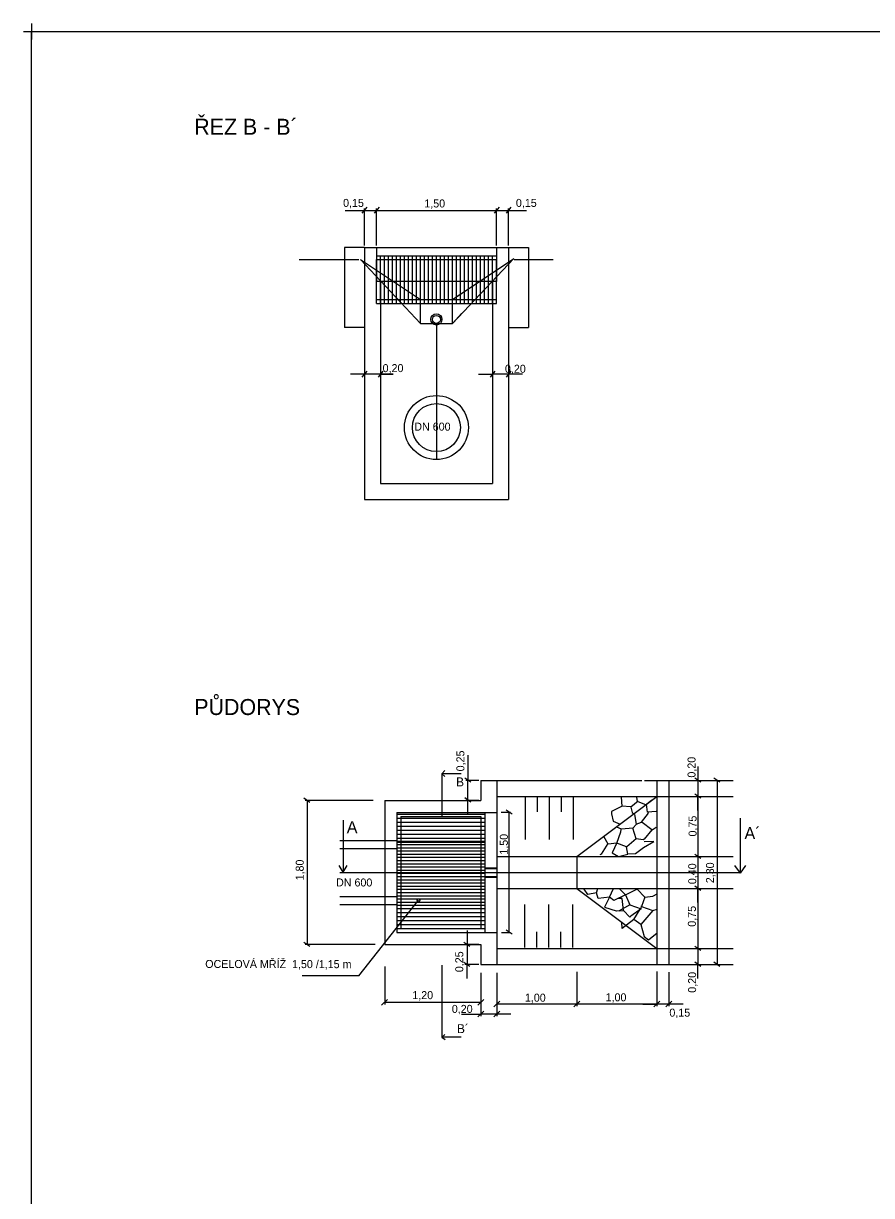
# Model space of a CAD drawing. Extents: x -463166.8 to -463145.6, y -1105023 to -1104993.1.
# Drawn here: x -463166.78 to -463156.18, y -1105007.73 to -1104993.08 of the extents above; entities that cross this region are included whole.
import ezdxf

# ---------------------------------------------------------------- set-up
doc = ezdxf.new("R2010")
doc.units = 0
doc.layers.add('Vrstva 14', color=7, linetype='Continuous')
doc.layers.add('Vrstva 57', color=7, linetype='Continuous')

msp = doc.modelspace()

# ---------------------------------------------------------------- linework, layer by layer
at = {"layer": 'Vrstva 14'}
for p, q in [((-463166.676, -1104993.078), (-463166.676, -1104993.278)), ((-463166.676, -1104993.078), (-463166.676, -1104993.278)), ((-463166.776, -1104993.178), (-463166.576, -1104993.178)), ((-463166.776, -1104993.178), (-463166.576, -1104993.178)), ((-463162.755, -1104995.415), (-463162.363, -1104995.415)), ((-463162.485, -1104995.376), (-463162.545, -1104995.45)), ((-463162.515, -1104995.515), (-463162.515, -1104995.39)), ((-463162.332, -1104995.376), (-463162.392, -1104995.45)), ((-463162.365, -1104995.853), (-463162.365, -1104995.39)), ((-463162.365, -1104995.637), (-463162.365, -1104995.391)), ((-463162.365, -1104995.416), (-463160.865, -1104995.416)), ((-463161.04, -1104995.415), (-463160.487, -1104995.415)), ((-463160.832, -1104995.376), (-463160.892, -1104995.45)), ((-463160.865, -1104995.515), (-463160.865, -1104995.39)), ((-463160.865, -1104995.637), (-463160.865, -1104995.391)), ((-463160.684, -1104995.376), (-463160.744, -1104995.45)), ((-463160.715, -1104995.853), (-463160.715, -1104995.39)), ((-463162.515, -1104995.853), (-463162.515, -1104995.515)), ((-463160.865, -1104995.853), (-463160.865, -1104995.515)), ((-463162.765, -1104995.878), (-463162.765, -1104996.878)), ((-463162.515, -1104995.878), (-463162.765, -1104995.878)), ((-463162.515, -1104995.878), (-463162.365, -1104995.878)), ((-463162.515, -1104995.878), (-463162.515, -1104997.122)), ((-463162.365, -1104995.878), (-463160.865, -1104995.878)), ((-463162.365, -1104995.878), (-463162.365, -1104996.303)), ((-463160.865, -1104995.878), (-463160.715, -1104995.878)), ((-463160.865, -1104995.878), (-463160.865, -1104996.303)), ((-463160.715, -1104995.878), (-463160.465, -1104995.878)), ((-463160.715, -1104995.878), (-463160.715, -1104997.122)), ((-463160.465, -1104995.878), (-463160.465, -1104996.878)), ((-463162.365, -1104995.982), (-463160.865, -1104995.982)), ((-463162.315, -1104996.581), (-463162.315, -1104995.982)), ((-463162.265, -1104996.581), (-463162.265, -1104995.982)), ((-463162.215, -1104996.581), (-463162.215, -1104995.982)), ((-463162.165, -1104996.581), (-463162.165, -1104995.982)), ((-463162.115, -1104996.581), (-463162.115, -1104995.982)), ((-463162.065, -1104996.581), (-463162.065, -1104995.982)), ((-463162.015, -1104996.581), (-463162.015, -1104995.982)), ((-463161.965, -1104996.581), (-463161.965, -1104995.982)), ((-463161.915, -1104996.581), (-463161.915, -1104995.982)), ((-463161.865, -1104996.581), (-463161.865, -1104995.982)), ((-463161.815, -1104996.581), (-463161.815, -1104995.982)), ((-463161.765, -1104996.581), (-463161.765, -1104995.982)), ((-463161.715, -1104996.581), (-463161.715, -1104995.982)), ((-463161.665, -1104996.581), (-463161.665, -1104995.982)), ((-463161.615, -1104996.581), (-463161.615, -1104995.982)), ((-463161.565, -1104996.47), (-463161.565, -1104995.982)), ((-463161.515, -1104996.468), (-463161.515, -1104995.982)), ((-463161.465, -1104996.467), (-463161.465, -1104995.982)), ((-463161.465, -1104996.467), (-463161.465, -1104995.982)), ((-463161.415, -1104996.465), (-463161.415, -1104995.982)), ((-463161.415, -1104996.528), (-463160.648, -1104996.017)), ((-463161.415, -1104996.828), (-463160.648, -1104996.017)), ((-463161.365, -1104996.464), (-463161.365, -1104995.982)), ((-463161.315, -1104996.578), (-463161.315, -1104995.982)), ((-463161.265, -1104996.578), (-463161.265, -1104995.982)), ((-463161.215, -1104996.578), (-463161.215, -1104995.982)), ((-463161.165, -1104996.578), (-463161.165, -1104995.982)), ((-463161.115, -1104996.578), (-463161.115, -1104995.982)), ((-463161.065, -1104996.578), (-463161.065, -1104995.982)), ((-463161.015, -1104996.581), (-463161.015, -1104995.982)), ((-463160.965, -1104996.581), (-463160.965, -1104995.982)), ((-463160.915, -1104996.581), (-463160.915, -1104995.982)), ((-463163.331, -1104996.028), (-463162.583, -1104996.028)), ((-463162.565, -1104996.028), (-463161.828, -1104996.52)), ((-463162.565, -1104996.028), (-463161.815, -1104996.828)), ((-463162.365, -1104996.578), (-463162.365, -1104996.028)), ((-463162.365, -1104996.028), (-463160.865, -1104996.028)), ((-463161.265, -1104996.461), (-463161.265, -1104996.028)), ((-463161.215, -1104996.459), (-463161.215, -1104996.028)), ((-463160.865, -1104996.578), (-463160.865, -1104996.028)), ((-463160.641, -1104996.028), (-463160.157, -1104996.028)), ((-463162.315, -1104996.303), (-463162.365, -1104996.303)), ((-463160.915, -1104996.303), (-463162.365, -1104996.303)), ((-463162.315, -1104996.303), (-463162.315, -1104996.578)), ((-463162.123, -1104996.303), (-463162.315, -1104996.303)), ((-463160.865, -1104996.303), (-463160.915, -1104996.303)), ((-463160.915, -1104996.303), (-463160.915, -1104997.122)), ((-463161.765, -1104996.581), (-463161.765, -1104996.467)), ((-463161.765, -1104996.581), (-463161.765, -1104996.467)), ((-463161.715, -1104996.581), (-463161.715, -1104996.465)), ((-463161.665, -1104996.581), (-463161.665, -1104996.464)), ((-463161.615, -1104996.581), (-463161.615, -1104996.462)), ((-463161.565, -1104996.581), (-463161.565, -1104996.461)), ((-463161.565, -1104996.581), (-463161.565, -1104996.461)), ((-463161.515, -1104996.581), (-463161.515, -1104996.459)), ((-463161.515, -1104996.581), (-463161.515, -1104996.459)), ((-463161.465, -1104996.581), (-463161.465, -1104996.458)), ((-463161.415, -1104996.581), (-463161.415, -1104996.456)), ((-463161.365, -1104996.581), (-463161.365, -1104996.455)), ((-463162.365, -1104996.528), (-463161.579, -1104996.528)), ((-463162.365, -1104996.578), (-463161.577, -1104996.578)), ((-463162.315, -1104996.578), (-463162.315, -1104997.122)), ((-463161.879, -1104996.528), (-463160.865, -1104996.528)), ((-463161.877, -1104996.578), (-463160.865, -1104996.578)), ((-463161.865, -1104996.581), (-463161.865, -1104996.47)), ((-463161.828, -1104996.52), (-463161.815, -1104996.528)), ((-463161.815, -1104996.528), (-463161.828, -1104996.52)), ((-463161.815, -1104996.581), (-463161.815, -1104996.468)), ((-463161.815, -1104996.828), (-463161.815, -1104996.528)), ((-463161.415, -1104996.528), (-463161.331, -1104996.472)), ((-463161.415, -1104996.828), (-463161.415, -1104996.528)), ((-463161.415, -1104996.828), (-463161.299, -1104996.705)), ((-463162.515, -1104996.878), (-463162.765, -1104996.878)), ((-463161.834, -1104996.808), (-463161.815, -1104996.828)), ((-463161.815, -1104996.828), (-463161.415, -1104996.828)), ((-463161.615, -1104996.828), (-463161.615, -1104997.122)), ((-463160.715, -1104996.878), (-463160.465, -1104996.878)), ((-463162.515, -1104997.036), (-463162.515, -1104997.486)), ((-463162.315, -1104997.036), (-463162.315, -1104997.486)), ((-463160.915, -1104997.036), (-463160.915, -1104997.486)), ((-463160.715, -1104997.036), (-463160.715, -1104997.486)), ((-463162.515, -1104997.122), (-463162.515, -1104999.028)), ((-463162.515, -1104997.187), (-463162.515, -1104997.622)), ((-463162.315, -1104997.122), (-463162.315, -1104998.828)), ((-463162.315, -1104997.155), (-463162.315, -1104997.486)), ((-463161.615, -1104997.122), (-463161.615, -1104998.528)), ((-463160.915, -1104997.122), (-463160.915, -1104998.828)), ((-463160.915, -1104997.155), (-463160.915, -1104997.486)), ((-463160.715, -1104997.122), (-463160.715, -1104999.028)), ((-463160.715, -1104997.187), (-463160.715, -1104997.622)), ((-463162.156, -1104997.461), (-463162.69, -1104997.461)), ((-463162.485, -1104997.426), (-463162.545, -1104997.5)), ((-463162.284, -1104997.426), (-463162.344, -1104997.5)), ((-463162.315, -1104997.461), (-463162.156, -1104997.461)), ((-463161.09, -1104997.461), (-463160.915, -1104997.461)), ((-463161.022, -1104997.461), (-463160.915, -1104997.461)), ((-463160.884, -1104997.424), (-463160.944, -1104997.498)), ((-463160.715, -1104997.461), (-463160.915, -1104997.461)), ((-463160.684, -1104997.424), (-463160.744, -1104997.498)), ((-463160.54, -1104997.461), (-463160.715, -1104997.461)), ((-463162.315, -1104998.828), (-463160.915, -1104998.828)), ((-463162.515, -1104999.028), (-463160.715, -1104999.028)), ((-463161.221, -1105002.222), (-463161.221, -1105002.54)), ((-463161.548, -1105002.456), (-463161.509, -1105002.414)), ((-463161.51, -1105002.492), (-463161.548, -1105002.456)), ((-463161.547, -1105002.456), (-463161.547, -1105002.985)), ((-463161.306, -1105002.456), (-463161.547, -1105002.456)), ((-463158.346, -1105002.365), (-463158.346, -1105002.54)), ((-463161.186, -1105002.562), (-463161.259, -1105002.511)), ((-463161.086, -1105002.54), (-463161.246, -1105002.54)), ((-463161.221, -1105002.79), (-463161.221, -1105002.54)), ((-463161.061, -1105002.54), (-463161.061, -1105002.79)), ((-463161.061, -1105002.54), (-463159.047, -1105002.54)), ((-463160.861, -1105002.54), (-463160.861, -1105004.84)), ((-463159.013, -1105002.54), (-463158.321, -1105002.54)), ((-463158.861, -1105002.54), (-463158.861, -1105003.49)), ((-463158.861, -1105002.54), (-463158.711, -1105002.54)), ((-463158.711, -1105002.54), (-463158.711, -1105004.84)), ((-463158.585, -1105002.54), (-463157.907, -1105002.54)), ((-463158.483, -1105002.54), (-463158.082, -1105002.54)), ((-463158.311, -1105002.562), (-463158.384, -1105002.511)), ((-463158.346, -1105002.54), (-463158.346, -1105002.74)), ((-463158.073, -1105002.562), (-463158.147, -1105002.511)), ((-463158.107, -1105002.54), (-463158.107, -1105004.84)), ((-463163.197, -1105002.814), (-463163.27, -1105002.763)), ((-463161.186, -1105002.809), (-463161.259, -1105002.758)), ((-463160.861, -1105002.74), (-463158.861, -1105002.74)), ((-463160.502, -1105003.277), (-463160.502, -1105002.74)), ((-463160.352, -1105002.933), (-463160.352, -1105002.74)), ((-463160.202, -1105003.277), (-463160.202, -1105002.74)), ((-463160.052, -1105002.933), (-463160.052, -1105002.74)), ((-463159.902, -1105003.277), (-463159.902, -1105002.74)), ((-463159.861, -1105003.49), (-463158.861, -1105002.74)), ((-463159.013, -1105002.74), (-463158.321, -1105002.74)), ((-463158.861, -1105002.74), (-463157.907, -1105002.74)), ((-463158.311, -1105002.762), (-463158.384, -1105002.711)), ((-463158.346, -1105002.915), (-463158.346, -1105002.74)), ((-463158.346, -1105002.74), (-463158.346, -1105003.49)), ((-463162.406, -1105002.79), (-463163.256, -1105002.79)), ((-463163.231, -1105002.79), (-463163.231, -1105004.59)), ((-463162.261, -1105002.79), (-463161.061, -1105002.79)), ((-463162.261, -1105002.79), (-463162.261, -1105004.59)), ((-463161.086, -1105002.79), (-463161.246, -1105002.79)), ((-463161.221, -1105002.965), (-463161.221, -1105002.79)), ((-463160.668, -1105002.962), (-463160.742, -1105002.911)), ((-463162.78, -1105003.037), (-463162.78, -1105003.684)), ((-463162.111, -1105002.94), (-463162.111, -1105004.44)), ((-463162.111, -1105002.94), (-463160.861, -1105002.94)), ((-463162.111, -1105002.94), (-463160.861, -1105002.94)), ((-463162.111, -1105002.96), (-463161.011, -1105002.96)), ((-463162.111, -1105003.01), (-463161.011, -1105003.01)), ((-463162.086, -1105002.94), (-463161.848, -1105002.94)), ((-463162.061, -1105002.99), (-463162.061, -1105004.39)), ((-463162.061, -1105002.99), (-463161.061, -1105002.99)), ((-463161.061, -1105002.99), (-463161.061, -1105004.39)), ((-463161.011, -1105002.94), (-463161.011, -1105004.44)), ((-463160.69, -1105002.941), (-463160.805, -1105002.941)), ((-463160.704, -1105004.44), (-463160.704, -1105002.94)), ((-463157.82, -1105003.009), (-463157.82, -1105003.7)), ((-463162.111, -1105003.06), (-463161.011, -1105003.06)), ((-463162.111, -1105003.11), (-463161.011, -1105003.11)), ((-463162.111, -1105003.16), (-463161.011, -1105003.16)), ((-463162.822, -1105003.29), (-463162.261, -1105003.29)), ((-463162.261, -1105003.29), (-463162.111, -1105003.29)), ((-463162.111, -1105003.21), (-463161.011, -1105003.21)), ((-463162.111, -1105003.26), (-463161.011, -1105003.26)), ((-463162.111, -1105003.3), (-463161.011, -1105003.3)), ((-463162.111, -1105003.31), (-463161.011, -1105003.31)), ((-463162.111, -1105003.34), (-463161.011, -1105003.34)), ((-463158.346, -1105003.315), (-463158.346, -1105003.49)), ((-463162.822, -1105003.39), (-463162.261, -1105003.39)), ((-463162.261, -1105003.39), (-463162.111, -1105003.39)), ((-463162.111, -1105003.38), (-463161.011, -1105003.38)), ((-463162.111, -1105003.42), (-463161.011, -1105003.42)), ((-463162.111, -1105003.46), (-463161.011, -1105003.46)), ((-463160.861, -1105003.49), (-463157.907, -1105003.49)), ((-463159.861, -1105003.49), (-463159.861, -1105003.89)), ((-463159.013, -1105003.49), (-463158.321, -1105003.49)), ((-463158.861, -1105003.49), (-463158.861, -1105003.89)), ((-463158.311, -1105003.517), (-463158.384, -1105003.465)), ((-463158.346, -1105003.49), (-463158.346, -1105003.89)), ((-463162.78, -1105003.684), (-463162.831, -1105003.601)), ((-463162.78, -1105003.684), (-463162.729, -1105003.601)), ((-463162.111, -1105003.5), (-463161.011, -1105003.5)), ((-463162.111, -1105003.54), (-463161.011, -1105003.54)), ((-463162.111, -1105003.58), (-463161.011, -1105003.58)), ((-463162.111, -1105003.62), (-463162.024, -1105003.62)), ((-463162.061, -1105003.62), (-463161.011, -1105003.62)), ((-463161.011, -1105003.63), (-463160.861, -1105003.63)), ((-463161.011, -1105003.64), (-463160.861, -1105003.64)), ((-463157.888, -1105003.602), (-463157.819, -1105003.7)), ((-463157.751, -1105003.602), (-463157.82, -1105003.7)), ((-463162.822, -1105003.69), (-463157.809, -1105003.69)), ((-463162.111, -1105003.66), (-463162.027, -1105003.66)), ((-463162.111, -1105003.7), (-463162.027, -1105003.7)), ((-463162.111, -1105003.74), (-463162.027, -1105003.74)), ((-463162.111, -1105003.78), (-463161.011, -1105003.78)), ((-463162.061, -1105003.66), (-463161.011, -1105003.66)), ((-463162.061, -1105003.7), (-463161.011, -1105003.7)), ((-463162.027, -1105003.74), (-463161.011, -1105003.74)), ((-463161.011, -1105003.74), (-463160.861, -1105003.74)), ((-463161.011, -1105003.75), (-463160.861, -1105003.75)), ((-463162.111, -1105003.82), (-463161.011, -1105003.82)), ((-463162.111, -1105003.86), (-463161.011, -1105003.86)), ((-463162.111, -1105003.9), (-463161.011, -1105003.9)), ((-463160.861, -1105003.89), (-463157.907, -1105003.89)), ((-463159.861, -1105003.89), (-463158.861, -1105004.64)), ((-463159.013, -1105003.89), (-463158.321, -1105003.89)), ((-463158.861, -1105003.89), (-463158.861, -1105004.84)), ((-463158.311, -1105003.915), (-463158.384, -1105003.863)), ((-463158.346, -1105004.065), (-463158.346, -1105003.89)), ((-463158.346, -1105003.89), (-463158.346, -1105004.64)), ((-463162.822, -1105003.99), (-463162.261, -1105003.99)), ((-463162.584, -1105004.981), (-463161.839, -1105004.037)), ((-463162.261, -1105003.99), (-463162.111, -1105003.99)), ((-463162.111, -1105003.94), (-463161.011, -1105003.94)), ((-463162.111, -1105003.98), (-463161.011, -1105003.98)), ((-463162.111, -1105004.02), (-463161.011, -1105004.02)), ((-463162.111, -1105004.06), (-463161.011, -1105004.06)), ((-463162.822, -1105004.09), (-463162.261, -1105004.09)), ((-463162.261, -1105004.09), (-463162.111, -1105004.09)), ((-463162.111, -1105004.1), (-463161.011, -1105004.1)), ((-463162.111, -1105004.14), (-463161.011, -1105004.14)), ((-463162.111, -1105004.19), (-463161.011, -1105004.19)), ((-463160.512, -1105004.089), (-463160.512, -1105004.626)), ((-463160.212, -1105004.089), (-463160.212, -1105004.626)), ((-463159.912, -1105004.089), (-463159.912, -1105004.626)), ((-463162.111, -1105004.24), (-463161.011, -1105004.24)), ((-463162.111, -1105004.29), (-463161.011, -1105004.29)), ((-463162.111, -1105004.34), (-463161.011, -1105004.34)), ((-463162.111, -1105004.39), (-463161.011, -1105004.39)), ((-463162.111, -1105004.44), (-463160.861, -1105004.44)), ((-463162.111, -1105004.44), (-463160.861, -1105004.44)), ((-463162.086, -1105004.44), (-463161.848, -1105004.44)), ((-463162.061, -1105004.39), (-463161.061, -1105004.39)), ((-463161.23, -1105004.415), (-463161.23, -1105004.59)), ((-463160.802, -1105004.439), (-463160.687, -1105004.439)), ((-463160.668, -1105004.462), (-463160.742, -1105004.411)), ((-463160.362, -1105004.433), (-463160.362, -1105004.626)), ((-463160.062, -1105004.433), (-463160.062, -1105004.626)), ((-463158.346, -1105004.465), (-463158.346, -1105004.64)), ((-463163.197, -1105004.615), (-463163.27, -1105004.563)), ((-463162.38, -1105004.59), (-463163.256, -1105004.59)), ((-463162.261, -1105004.59), (-463161.061, -1105004.59)), ((-463161.196, -1105004.616), (-463161.27, -1105004.564)), ((-463161.086, -1105004.59), (-463161.255, -1105004.59)), ((-463161.23, -1105004.59), (-463161.23, -1105004.84)), ((-463161.061, -1105004.59), (-463161.061, -1105004.84)), ((-463160.861, -1105004.64), (-463158.861, -1105004.64)), ((-463159.013, -1105004.64), (-463158.321, -1105004.64)), ((-463159.013, -1105004.64), (-463158.321, -1105004.64)), ((-463158.648, -1105004.64), (-463157.907, -1105004.64)), ((-463158.311, -1105004.665), (-463158.384, -1105004.614)), ((-463158.346, -1105004.64), (-463158.346, -1105004.84)), ((-463161.196, -1105004.864), (-463161.27, -1105004.813)), ((-463158.311, -1105004.864), (-463158.384, -1105004.812)), ((-463158.073, -1105004.863), (-463158.147, -1105004.812)), ((-463162.261, -1105004.865), (-463162.261, -1105005.338)), ((-463161.547, -1105004.847), (-463161.547, -1105005.748)), ((-463161.086, -1105004.84), (-463161.255, -1105004.84)), ((-463161.23, -1105005.015), (-463161.23, -1105004.84)), ((-463161.061, -1105004.84), (-463159.013, -1105004.84)), ((-463161.061, -1105004.945), (-463161.061, -1105005.484)), ((-463160.861, -1105004.943), (-463160.861, -1105005.359)), ((-463159.861, -1105004.93), (-463159.861, -1105005.359)), ((-463159.013, -1105004.84), (-463158.321, -1105004.84)), ((-463158.861, -1105004.84), (-463158.711, -1105004.84)), ((-463158.861, -1105004.926), (-463158.861, -1105005.359)), ((-463158.711, -1105004.937), (-463158.711, -1105005.359)), ((-463158.619, -1105004.84), (-463158.597, -1105004.84)), ((-463158.483, -1105004.84), (-463158.082, -1105004.84)), ((-463158.346, -1105005.015), (-463158.346, -1105004.84)), ((-463158.082, -1105004.84), (-463157.907, -1105004.84)), ((-463162.584, -1105004.981), (-463163.294, -1105004.981)), ((-463162.299, -1105005.349), (-463162.225, -1105005.278)), ((-463161.061, -1105005.313), (-463162.261, -1105005.313)), ((-463161.097, -1105005.349), (-463161.024, -1105005.278)), ((-463160.896, -1105005.369), (-463160.822, -1105005.298)), ((-463159.861, -1105005.334), (-463160.861, -1105005.334)), ((-463160.861, -1105005.359), (-463160.861, -1105005.484)), ((-463159.896, -1105005.369), (-463159.823, -1105005.298)), ((-463158.861, -1105005.334), (-463159.861, -1105005.334)), ((-463159.036, -1105005.334), (-463158.861, -1105005.334)), ((-463158.897, -1105005.369), (-463158.823, -1105005.298)), ((-463158.711, -1105005.334), (-463158.861, -1105005.334)), ((-463158.746, -1105005.369), (-463158.673, -1105005.298)), ((-463158.532, -1105005.334), (-463158.711, -1105005.334)), ((-463161.303, -1105005.459), (-463161.061, -1105005.459)), ((-463161.097, -1105005.494), (-463161.024, -1105005.423)), ((-463160.861, -1105005.459), (-463161.061, -1105005.459)), ((-463160.896, -1105005.494), (-463160.823, -1105005.423)), ((-463160.686, -1105005.459), (-463160.861, -1105005.459)), ((-463161.547, -1105005.748), (-463161.511, -1105005.714)), ((-463161.306, -1105005.748), (-463161.547, -1105005.748)), ((-463161.547, -1105005.748), (-463161.504, -1105005.779))]:
    msp.add_line(p, q, dxfattribs=at)
msp.add_lwpolyline([(-463166.676, -1104993.178), (-463145.676, -1104993.178), (-463145.676, -1105022.878), (-463166.676, -1105022.878)], close=True, dxfattribs=at)
for points in [[(-463159.19, -1105002.87), (-463159.293, -1105002.861), (-463159.302, -1105002.748)], [(-463158.987, -1105002.847), (-463159.1, -1105002.802), (-463159.109, -1105002.748)], [(-463159.293, -1105002.861), (-463159.428, -1105002.928), (-463159.428, -1105002.956), (-463159.406, -1105003.05), (-463159.32, -1105003.086)], [(-463159.095, -1105002.798), (-463159.185, -1105002.874), (-463159.167, -1105002.942), (-463159.149, -1105002.956)], [(-463158.866, -1105002.928), (-463158.978, -1105002.937), (-463158.987, -1105002.838), (-463158.924, -1105002.78)], [(-463159.14, -1105002.965), (-463159.118, -1105003.086), (-463159.05, -1105003.059), (-463158.965, -1105002.947), (-463158.974, -1105002.933)], [(-463159.041, -1105003.059), (-463158.924, -1105003.154), (-463158.92, -1105003.158), (-463158.866, -1105003.122)], [(-463159.158, -1105003.136), (-463159.302, -1105003.149), (-463159.361, -1105003.122)], [(-463159.118, -1105003.271), (-463159.235, -1105003.37), (-463159.239, -1105003.37), (-463159.361, -1105003.325), (-463159.311, -1105003.181), (-463159.307, -1105003.154)], [(-463158.924, -1105003.158), (-463159.019, -1105003.275), (-463159.032, -1105003.28), (-463159.118, -1105003.271), (-463159.158, -1105003.136), (-463159.113, -1105003.086)], [(-463159.473, -1105003.329), (-463159.554, -1105003.46), (-463159.572, -1105003.469)], [(-463159.361, -1105003.325), (-463159.469, -1105003.334), (-463159.523, -1105003.239)], [(-463159.361, -1105003.32), (-463159.419, -1105003.446), (-463159.338, -1105003.491), (-463159.221, -1105003.46), (-463159.239, -1105003.37)], [(-463159.226, -1105003.455), (-463159.127, -1105003.451), (-463159.028, -1105003.379), (-463158.897, -1105003.302), (-463159.019, -1105003.307)], [(-463159.613, -1105003.946), (-463159.721, -1105003.964), (-463159.77, -1105003.897)], [(-463159.451, -1105004), (-463159.595, -1105004.014), (-463159.613, -1105003.946), (-463159.599, -1105003.892)], [(-463159.253, -1105003.969), (-463159.397, -1105004.041), (-463159.451, -1105004), (-463159.401, -1105003.892)], [(-463159.253, -1105003.969), (-463159.329, -1105003.892)], [(-463159.104, -1105003.897), (-463159.239, -1105003.964), (-463159.253, -1105003.969), (-463159.199, -1105004.095), (-463159.055, -1105004.144), (-463159.05, -1105004.108)], [(-463159.104, -1105003.897), (-463159.01, -1105004), (-463158.911, -1105003.987), (-463158.857, -1105003.955)], [(-463159.451, -1105004), (-463159.514, -1105004.122), (-463159.37, -1105004.171), (-463159.365, -1105004.171), (-463159.275, -1105004.167), (-463159.293, -1105004.014), (-463159.338, -1105004.014)], [(-463159.01, -1105004), (-463159.05, -1105004.117), (-463158.911, -1105004.167), (-463158.857, -1105004.149)], [(-463159.199, -1105004.095), (-463159.329, -1105004.171), (-463159.275, -1105004.167)], [(-463158.911, -1105004.167), (-463159.059, -1105004.342), (-463159.149, -1105004.279), (-463159.068, -1105004.149), (-463159.055, -1105004.144), (-463159.185, -1105004.234), (-463159.199, -1105004.248), (-463159.275, -1105004.167)], [(-463159.149, -1105004.279), (-463159.293, -1105004.392), (-463159.298, -1105004.311)], [(-463159.059, -1105004.342), (-463159.019, -1105004.491), (-463158.965, -1105004.531), (-463158.857, -1105004.446)]]:
    msp.add_lwpolyline(points, dxfattribs=at)
for centre, radius in [((-463161.615, -1104996.778), 0.07), ((-463161.615, -1104996.778), 0.05), ((-463161.615, -1104998.129), 0.4), ((-463161.615, -1104998.129), 0.3), ((-463161.839, -1105004.037), 0.0171)]:
    msp.add_circle(centre, radius, dxfattribs=at)

# ---------------------------------------------------------------- texts
for s, p in [('0,15', (-463162.781, -1104995.371)), ('1,50', (-463161.766, -1104995.378)), ('0,15', (-463160.621, -1104995.371)), ('0,20', (-463162.287, -1104997.436)), ('0,20', (-463160.758, -1104997.444)), ('1,20', (-463161.916, -1105005.273)), ('1,00', (-463160.509, -1105005.305)), ('1,00', (-463159.5, -1105005.3)), ('0,20', (-463161.422, -1105005.445)), ('0,15', (-463158.703, -1105005.492))]:
    msp.add_text(s, height=0.1, dxfattribs=at).set_placement(p)
for s, p in [('0,25', (-463161.265, -1105002.426)), ('0,20', (-463158.376, -1105002.504)), ('0,75', (-463158.363, -1105003.24)), ('1,50', (-463160.722, -1105003.468)), ('1,80', (-463163.273, -1105003.789)), ('0,40', (-463158.367, -1105003.836)), ('2,30', (-463158.145, -1105003.824)), ('0,75', (-463158.372, -1105004.368)), ('0,25', (-463161.279, -1105004.936)), ('0,20', (-463158.369, -1105005.193))]:
    msp.add_text(s, height=0.1, rotation=90, dxfattribs=at).set_placement(p)
at = {"layer": 'Vrstva 57'}
for s, height, rotation, p in [('ŘEZ B - B´', 0.2, 359.9224, (-463164.641, -1104994.468)), ('DN 600', 0.1, 359.903, (-463161.891, -1104998.167)), ('PŮDORYS', 0.2, 359.9224, (-463164.641, -1105001.721)), ('B', 0.112, 359.9224, (-463161.369, -1105002.614)), ('A', 0.15, 359.9224, (-463162.735, -1105003.199)), ('A´', 0.15, 359.9224, (-463157.764, -1105003.272)), ('DN 600', 0.1, 359.903, (-463162.869, -1105003.864)), ('OCELOVÁ MŘÍŽ  1,50 /1,15 m', 0.1, 359.903, (-463164.504, -1105004.883)), ('B´', 0.112, 359.9224, (-463161.358, -1105005.698))]:
    msp.add_text(s, height=height, rotation=rotation, dxfattribs=at).set_placement(p)

doc.saveas('drawing.dxf')
